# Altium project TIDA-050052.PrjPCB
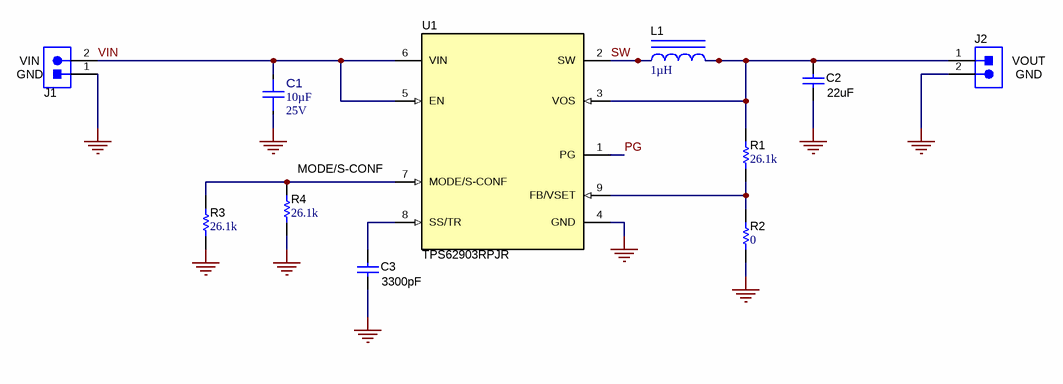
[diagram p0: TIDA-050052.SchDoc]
CopyrightYear: 2018; PCB_Layout: Fred Illguth; PCB_Rev: A; PRJ_Customer: Public Release; PRJ_Engineer: Tahar Allag; PRJ_Number: TIDA-050052; PRJ_Title: TPS6290X; SCH_Rev: A; TechSupport: http://www.ti.com/support; TIDA: N/A
2 sheets, 22 parts. Net scope: global (net labels, ports and power ports of the same name join across sheets).
Board file: TIDA-050052.PcbDoc
Sheets:
  TIDA-050052.SchDoc
  TIDA-050052_Hardware.SchDoc

## Sheet TIDA-050052.SchDoc
size 558 x 431 mm; Date: Not shown in title block; ApprovedBy: Not shown in title block; CheckedBy: Not shown in title block; Author: Tahar allag; CompanyName: Not shown in title block; DrawnBy: Tahar Allag; Engineer: Tahar allag; Organization: Not shown in title block; Address1: Not shown in title block; Address2: Not shown in title block; Address3: Not shown in title block; Address4: Not shown in title block; DocumentNumber: 1; Revision: Use project parameter SCH_Rev; SheetNumber: 1; SheetTotal: 2; PageSetup: Record=PageOptions¦CenterHorizontal=True¦CenterVertical=True¦PrintScale=1.00¦XCorrection=1.00¦YCorrection=1.00¦PrintKind=0¦BorderSize=5000000¦LeftOffset=0¦BottomOffset=0¦Orientation=2¦PaperLength=1000¦PaperWidth=1000¦Scale=100¦PaperSource=15¦PrintQuality=600¦MediaType=1¦DitherType=10¦PaperKind=Letter¦PrintScaleMode=1

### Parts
C1  Cap_F: 10µF  VDC_V: 25V  [FP-GMC21X7R106K25NT_0805-MFG]  (hidden comment: GMC21X7R106K25NT)
C2  ValueDisplayed: 22uF  [0805_HV1]  (hidden comment: C2012X7S1A226M125AC)
C3  ValueDisplayed: 3300pF  [0603S]  (hidden comment: GRM1885C1H332JA01D)
J1  61300211121  [WURTH_61300211121]  (value not drawn)
J2  61300211121  [WURTH_61300211121]  (value not drawn)
L1  ValueDisplayed: 1µH  [DFE201612E]  (hidden comment: DFE201612E-1R0M=P2)
R1  ValueDisplayed: 26.1k  [0603]  (hidden comment: RC0603FR-0726K1L)
R2  ValueDisplayed: 0  [0603]  (hidden comment: RC0603JR-070RL)
R3  ValueDisplayed: 26.1k  [0402]  (hidden comment: CRCW040226K1FKED)
R4  ValueDisplayed: 26.1k  [0603]  (hidden comment: RC0603FR-0726K1L)
U1  TPS62903RPJR  [RPJ0009A]

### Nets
GND: C1.1 C2.2 C3.2 J1.1 J2.2 R2.1 R3.1 R4.1 U1.4(GND)
PG: U1.1(PG)
SW: L1.1 U1.2(SW)
VIN: C1.2 J1.2 U1.5(EN) U1.6(VIN)
NetC2_1: C2.1 J2.1 L1.2 R1.2 U1.3(VOS)
NetC3_1: C3.1 U1.8(SS/TR)
NetR1_1: R1.1 R2.2 U1.9(FB/VSET)
NetR3_2: R3.2 R4.2 U1.7(MODE/S-CONF)

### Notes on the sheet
- (near J1) VIN
- (near J1) GND
- (near J2) VOUT
- (near J2) GND
- (near R4) MODE/S-CONF

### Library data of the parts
C1 = CMP-0092369-1: CAP0805 X7R 10UF 10% 25V; Manufacturer: Cal-Chip Electronics; TempCo: 15%; Value: 10µF; SizeZ_mm: 1.5mm; AEC Qualified: No
C2 = CMP-0007890-2: CAP, CERM, 22 uF, 10 V, +/- 20%, X7S, 0805; Manufacturer: TDK; TaMin_C: -55°C; ESR_ohm: 2.05m; Polarized: N; SizeAreaWB_mm2: 6.75; Value1: 0.00205 ohm; U/M: EA; Value: 22uF; TaMax_C: 125°C; SizeZ_mm: 1.45; SizeX_mm: 2; SizeY_mm: 1.25; Cap_Case: 0805; Value2: 10V; SizeArea_mm2: 2.5; Cap_F: 22µF; IRMS_A: 4.55587A; AEC Category: Q200
C3 = CMP-0007210-4: CAP, CERM, 3300 pF, 50 V, +/- 5%, C0G/NP0, 0603; Manufacturer: MuRata; TaMin_C: -55°C; Polarized: N; SizeAreaWB_mm2: 4.68; Value1: Unknown; U/M: EA; Value: 3300pF; TaMax_C: 125°C; SizeZ_mm: 1; SizeX_mm: 1.6; SizeY_mm: 0.8; Cap_Case: 0603; Value2: 50V; SizeArea_mm2: 1.28; Cap_F: 3.3nF; AEC Category: Q200
J1 J2 = CMP-0054794-2: Header, 2.54 mm, 2x1, Gold, TH; Manufacturer: Wurth Elektronik; Shrouded: N; Gender: Male; Green_REACh: Passed; Pitch_mm: 2.54; Green_Lifecycle: Active; Row_Count: 1; Cert_UL: Y
L1 = CMP-0080773-1: Inductor, Shielded, Metal Composite, 1 µH, 2.9 A, 0.048 ohm, SMD; Manufacturer: MuRata; Isat: 4A @ 30% inductance drop; Irms: 2.9A @ 40C rise; SizeAreaWB_mm2: 7.8; DCR_ohm: 0.048; Value: 1uH; Imax_A: 2.9A; SizeZ_mm: 1.2; SizeX_mm: 2; SizeY_mm: 1.6; SizeArea_mm2: 3.2; AEC Qualified: N; AEC Category: Q200
R1 R4 = CMP-0022957-2: RES, 26.1 k, 1%, 0.1 W, 0603; Manufacturer: Yageo America; Power_W: 100mW; TempCo: 200 ppm/C; Value_Code: 26k1; U/M: EA; Value: 26.1k; EIA_Code: E96; SizeX_mm: 1.6; SizeY_mm: 0.8; SizeZ_mm: 1; Value2: 0.1W; SizeArea_mm2: 1.28; VDC_V: 150V; AEC Category: Q200
R2 = CMP-0025885-1: RES, 0, 5%, 0.1 W, 0603; Manufacturer: Yageo America; Power_W: 100mW; TempCo: 200 ppm/C; Value_Code: 0000; U/M: EA; Value: 0; EIA_Code: E24; SizeX_mm: 1.6; SizeZ_mm: 1; Value2: 0.1W; SizeArea_mm2: 1.28; VDC_V: 50V; AEC Category: Q200; SizeY_mm: 0.8
R3 = CMP-0026207-1: RES, 26.1 k, 1%, 0.063 W, 0402; Manufacturer: Vishay-Dale; Power_W: 63mW; TempCo: 100 ppm/C; Value_Code: 26k1; U/M: EA; Value: 26.1k; EIA_Code: E96; SizeX_mm: 1; SizeY_mm: 0.5; SizeZ_mm: 0.6; Value2: 0.063W; VDC_V: 50V; AEC Category: Q200
U1 = CMP-0084866-4: 2.9-V to 18-V, 3-A Synchronous Buck Converters, RPJ0009A (VQFN-HR-9); Alternate Manufacturer: Texas Instruments; Alternate PartNumber: TPS62903RPJT; SizeArea_mm2: 3; AEC Category: Q200; SizeX_mm: 1.5; AEC Qualified: N; CompType: IC; SizeAreaWB_mm2: 7.5; SizeY_mm: 2; SizeZ_mm: 1

## Sheet TIDA-050052_Hardware.SchDoc
size 431 x 279 mm; Date: Not shown in title block; ApprovedBy: Not shown in title block; CheckedBy: Not shown in title block; Author: Not shown in title block; CompanyName: Not shown in title block; DrawnBy: Chris Glaser; Engineer: Not shown in title block; Organization: Not shown in title block; Address1: Not shown in title block; Address2: Not shown in title block; Address3: Not shown in title block; Address4: Not shown in title block; DocumentNumber: 2; Revision: Use project parameter SCH_Rev; SheetNumber: 2; SheetTotal: 2; PageSetup: Record=PageOptions¦CenterHorizontal=True¦CenterVertical=True¦PrintScale=1.00¦XCorrection=1.00¦YCorrection=1.00¦PrintKind=0¦BorderSize=5000000¦LeftOffset=0¦BottomOffset=0¦Orientation=2¦PaperLength=1000¦PaperWidth=1000¦Scale=100¦PaperSource=15¦PrintQuality=600¦MediaType=1¦DitherType=10¦PaperKind=Letter¦PrintScaleMode=1
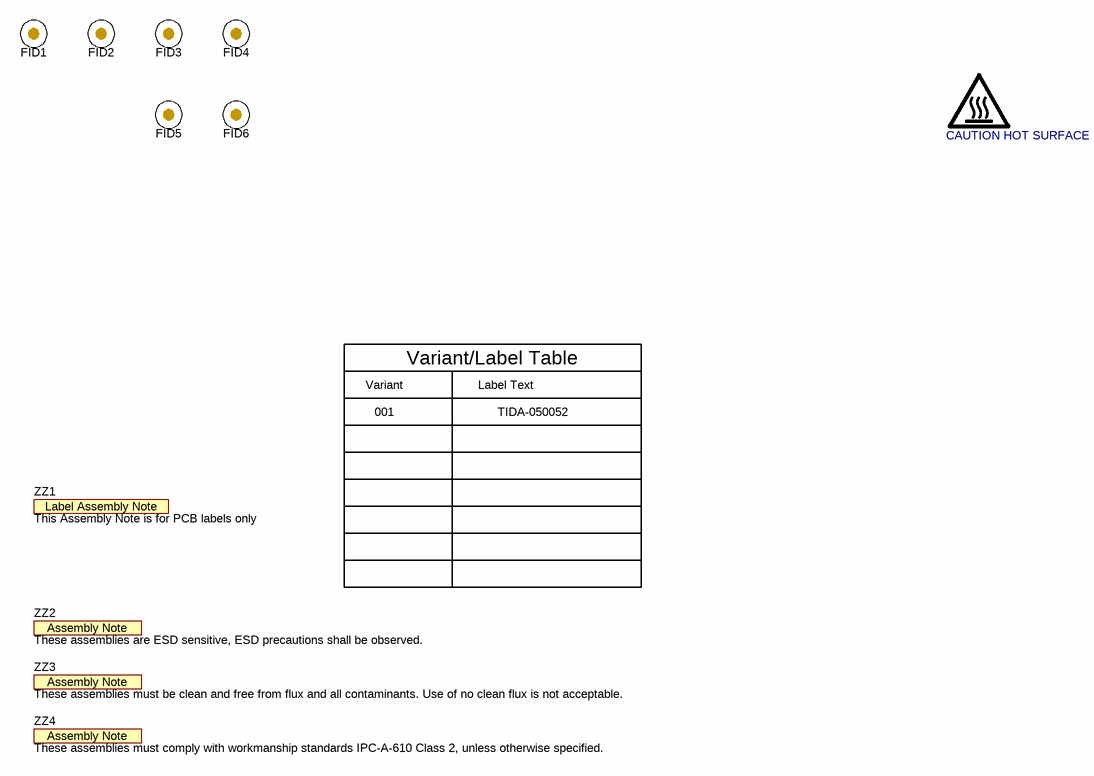
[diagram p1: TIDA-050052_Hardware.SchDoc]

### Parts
FID1  Fiducial  [Fiducial10-20]  (value not drawn)
FID2  Fiducial  [Fiducial10-20]  (value not drawn)
FID3  Fiducial  [Fiducial10-20]  (value not drawn)
FID4  Fiducial  [Fiducial10-20]  (value not drawn)
FID5  Fiducial  [Fiducial10-20]  (value not drawn)
FID6  Fiducial  [Fiducial10-20]  (value not drawn)
ZZ1  This Assembly Note is for PCB labels only  [AssemblyNoteLabel]  (no BOM)
ZZ2  These assemblies are ESD sensitive, ESD precautions shall be observed.  [AssemblyNote]  (no BOM)
ZZ3  These assemblies must be clean and free from flux and all contaminants. Use of no clean flux is not acceptable.  [AssemblyNote]  (no BOM)
ZZ4  These assemblies must comply with workmanship standards IPC-A-610 Class 2, unless otherwise specified.  [AssemblyNote]  (no BOM)
  CAUTION HOT SURFACE  [IEC_HotSurface_Small]  (no BOM)

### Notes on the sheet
- Variant
- Variant/Label Table
- Label Text
- 001
- TIDA-050052

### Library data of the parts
FID1-FID6 = CMP-0077181-1: Fiducial mark.  There is nothing to buy or mount.
ZZ1 = CMP-0003616-3
ZZ2 = CMP-0077236-1
ZZ3 = CMP-0077237-1
ZZ4 = CMP-0077238-1
 = CMP-0074837-1: IEC 61010-1 Hot Surface Warning; SymbolCreator: a0412235

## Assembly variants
001: not fitted C3 FID1 FID2 FID3 FID4 R1 R4; alternate parts U1 -> CMP-0084864-4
